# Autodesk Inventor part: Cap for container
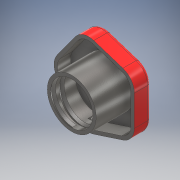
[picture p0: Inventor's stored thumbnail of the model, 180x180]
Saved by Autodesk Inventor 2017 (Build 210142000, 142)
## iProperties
Created: 2020-03
Part Number: Cap for container
Material: Steel, Galvanized
Document SubType Name: Modeling
Designer: user
Density: 7.85 g/cm^3
Appearance: Galvanized
Author: user
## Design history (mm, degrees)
sketch "Sketch1"
  geometry: C1 r 12.7 at (0, 0); C2 r 14.7 at (0, 0); 1 further point
  constraints: 2 centre point, 1 coincident
  dimensions: "d0" = 25.4 diameter of C1; "d1" = 2 radial gap between concentric circles of C1 C2
extrude "Extrusion1" new body sketch "Sketch1" distance "d2" = 15; taper "d3" = 0 deg
sketch "Sketch2"
  geometry: L1 (0, -12.7)-(15, -12.7) reference; L2 (0, -12.7)-(3, -12.7); L3 (3, -12.7)-(1.5, -13.7); L4 (1.5, -13.7)-(0, -12.7); 1 further point
  constraints: 6 end point, 2 point on line
  dimensions: "d4" = 3 distance of L2.start L2.end; "d5" = 1 distance from line of L1 L3.end; "d6" = 1.5 horizontal distance of L2.start L3.end
sketch "Sketch3"
  geometry: L1 (0, 0)-(18.337, 0)
  constraints: 2 end point, 1 horizontal
coil "Coil1" sketch "Sketch2", "Sketch3" pitch "d7" = 6; turns "d9" = 1.5; dims "d8" = 10, "d10" = 0, angle "d11" = 90 deg, angle "d12" = 90 deg, "d13" = 0, "d14" = 0
sketch "Sketch4"
  geometry: L1 (-23.75, 5.878)-(-12.929, 20.771); L2 (-1.749, 24.404)-(15.759, 18.715); L3 (22.669, 9.205)-(22.669, -9.205); L4 (15.759, -18.715)-(-1.749, -24.404); L5 (-12.929, -20.771)-(-23.75, -5.878); A1 r 10 centre (-4.839, -14.893) between (-12.929, -20.771) and (-1.749, -24.404); A2 r 10 centre (-15.66, 0) between (-23.75, 5.878) and (-23.75, -5.878); A3 r 10 centre (-4.839, 14.893) between (-1.749, 24.404) and (-12.929, 20.771); A4 r 10 centre (12.669, 9.205) between (22.669, 9.205) and (15.759, 18.715); A5 r 10 centre (12.669, -9.205) between (15.759, -18.715) and (22.669, -9.205); 7 further points
  constraints: 10 end point, 10 point on circle, 10 point on line, 10 tangent, 5 centre point, 4 equal radius, 1 coincident, 11 other
  dimensions: "d15" = 10 radius of A1 (derived)
extrude "Extrusion2" join sketch "Sketch4" distance "d16" = 10; taper "d17" = 0 deg
shell "Shell1" dims "d18" = 2
sketch "Sketch5"
  geometry: C1 r 14.7 at (0, 0); 1 further point
  constraints: 1 centre point, 1 coincident
extrude "Extrusion3" join sketch "Sketch5" stored distance "d19" = 10; taper "d20" = 0 deg
fillet "Fillet1" dims "d21" = 2
body "Solid1"
